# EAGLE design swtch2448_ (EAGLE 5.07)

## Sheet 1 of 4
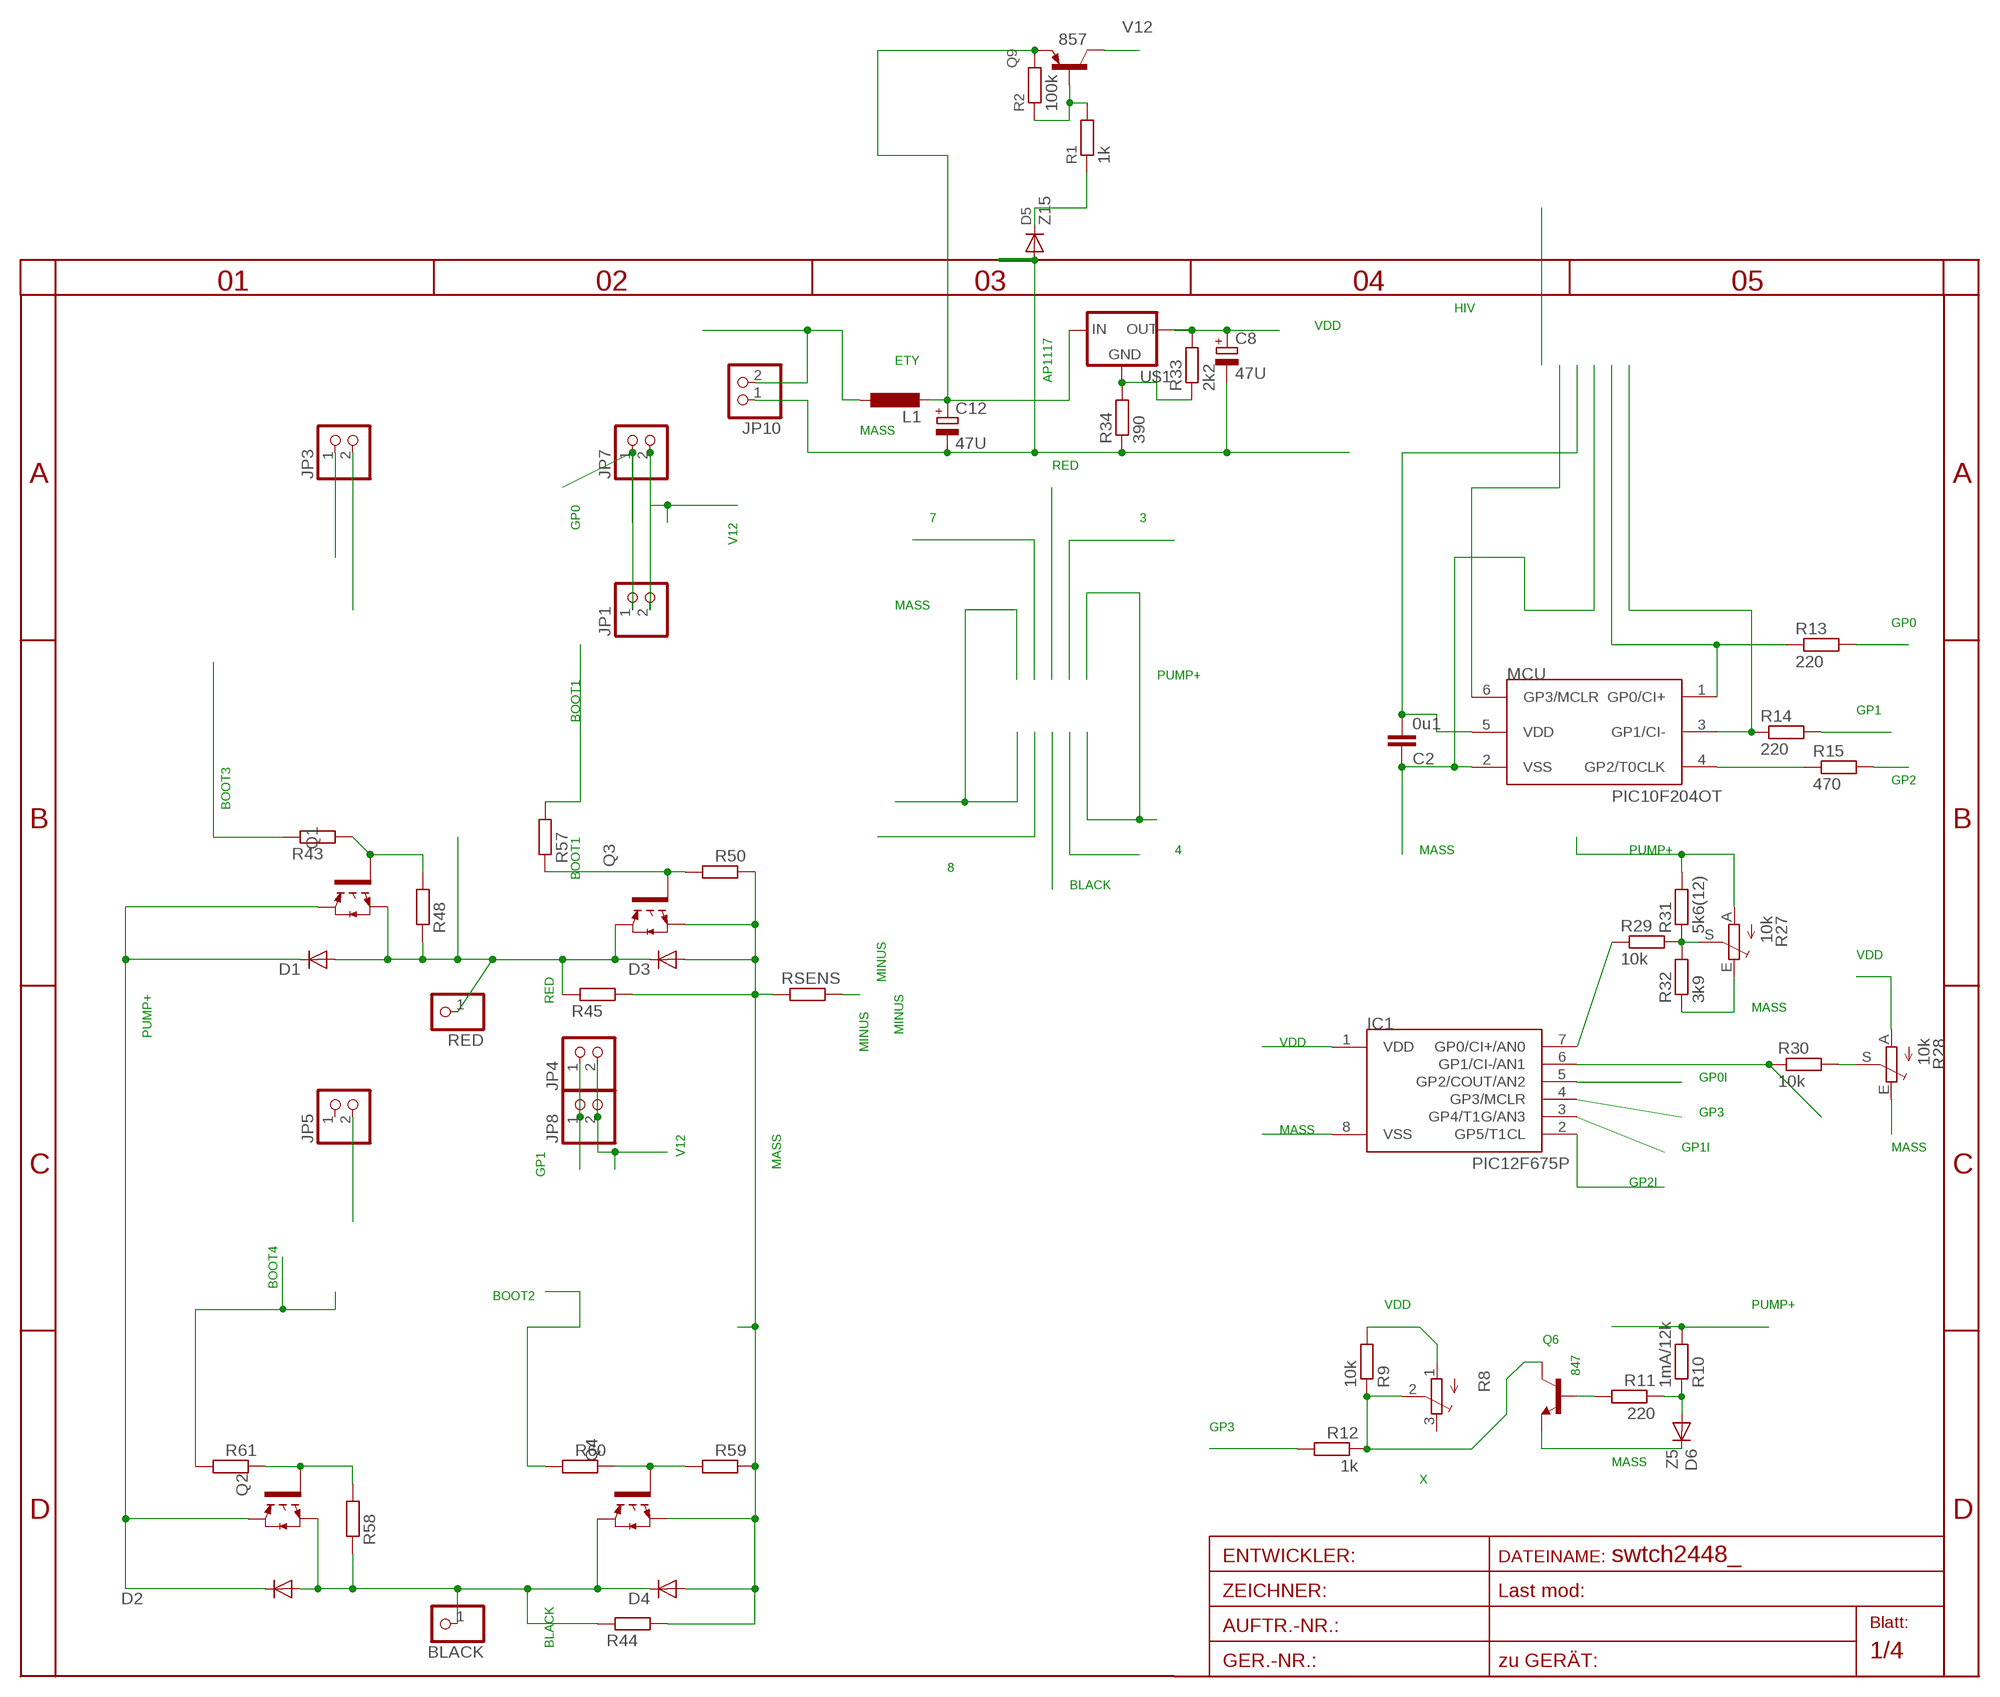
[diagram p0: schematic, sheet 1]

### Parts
BLACK  PINHD-1X14.5MM  [1X4MM5]
C2  0u1  C-EUC0805  [C0805]
C8  47U  CPOL-EUE  [PANASONIC_E]
C12  47U  CPOL-EUE  [PANASONIC_E]
D1  DIODE-SMC  [SMC]
D2  DIODE-SMC  [SMC]
D3  DIODE-SMC  [SMC]
D4  DIODE-SMC  [SMC]
D5  Z15  DIODE-MINIMELF  [MINIMELF]
D6  Z5  DIODE-MINIMELF  [MINIMELF]
IC1  PIC12F675P  [DIL8]
JP1  PINHD-1X2STR  [1X02]
JP3  PINHD-1X2STR  [1X02]
JP4  PINHD-1X2STR  [1X02]
JP5  PINHD-1X2STR  [1X02]
JP7  PINHD-1X2STR  [1X02]
JP8  PINHD-1X2STR  [1X02]
JP10  PINHD-1X2STR  [1X02]
L1  L-EU0204/5  [0204/5]
MCU  PIC10F204OT  [SOT23-6]
Q1  IRG4BC15UD-S  [D2PACK]
Q2  IRG4BC15UD-S  [D2PACK]
Q3  IRG4BC15UD-S  [D2PACK]
Q4  IRG4BC15UD-S  [D2PACK]
Q6  847  BC847ALT1SMD  [SOT23]
Q9  857  BC857ALT1SMD  [SOT23-BEC]
R1  1k  R-EU_R0805  [R0805]
R2  100k  R-EU_R0805  [R0805]
R8  TRIM_EU-3223W  [3223W]
R9  10k  R-EU_R1206  [R1206]
R10  1mA/12k  R-EU_R1206  [R1206]
R11  220  R-EU_R1206  [R1206]
R12  1k  R-EU_0204/7  [0204/7]
R13  220  R-EU_R1206  [R1206]
R14  220  R-EU_0207/10  [0207/10]
R15  470  R-EU_0207/20  [0207/20]
R27  10k  TRIM_EU-RAND160  [RANDL]
R28  10k  TRIM_EU-RAND160  [RANDL]
R29  10k  R-EU_0207/30  [0207/30]
R30  10k  R-EU_R0805  [R0805]
R31  5k6(12)  R-EU_0207/30  [0207/30]
R32  3k9  R-EU_R0805  [R0805]
R33  2k2  R-EU_R0805  [R0805]
R34  390  R-EU_R0805  [R0805]
R43  R-EU_0204/2V  [0204V]
R44  R-EU_0204/2V  [0204V]
R45  R-EU_0204/2V  [0204V]
R48  R-EU_R1206  [R1206]
R50  R-EU_R1206  [R1206]
R57  R-EU_0204/2V  [0204V]
R58  R-EU_R1206  [R1206]
R59  R-EU_R1206  [R1206]
R60  R-EU_0204/2V  [0204V]
R61  R-EU_0204/2V  [0204V]
RED  PINHD-1X14.5MM  [1X4MM5]
RSENS  R-EU_CERAM55  [CERAM55]
U$1  AP1117  [SOT223]

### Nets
BLACK: BLACK.1 D2.A D4.C Q2.3(E) Q4.2(C) R44.1 R58.1 ; also sheet 2
BOOT1: R57.2 ; also sheet 2
BOOT2: R60.2 ; also sheet 2
BOOT3: R43.1 ; also sheet 2
BOOT4: R61.2 ; also sheet 2
ETY: JP10.2 L1.1
GP0: JP1.1 JP7.1 R13.2 ; also sheet 2
GP0I: IC1.5(GP2/COUT/AN2) MCU.1(GP0/CI+) R13.1
GP1: JP3.1 JP4.1 JP8.1 R14.2 ; also sheet 2
GP1I: IC1.3(GP4/T1G/AN3) MCU.3(GP1/CI-) R14.1
GP2: R15.2 ; also sheet 2
GP2I: IC1.2(GP5/T1CL) MCU.4(GP2/T0CLK) R15.1
GP3: IC1.4(GP3/MCLR) MCU.6(GP3/MCLR) R12.2
MASS: C2.1 C8.- C12.- D3.A D4.A D5.A D6.C IC1.8(VSS) JP10.1 MCU.2(VSS) Q3.3(E) Q4.3(E) Q6.2(E) R27.E R28.E R32.1 R34.1 R44.2 R45.2 R50.1 R59.1 RSENS.1 ; also sheet 2
MINUS: RSENS.2 ; also sheet 2,3,4
N$1: C12.+ L1.2 Q9.E R2.2 U$1.3(IN)
N$2: Q9.B R1.2 R2.1
N$3: D5.C R1.1
N$4: D6.A R10.1 R11.1
N$5: Q6.1(B) R11.2
N$14: Q1.1(G) R43.2 R48.2
N$24: R28.S R30.2
N$30: R33.1 R34.2 U$1.1(GND)
N$31: IC1.6(GP1/CI-/AN1) R30.1
N$34: R27.S R29.2 R31.1 R32.2
N$35: IC1.7(GP0/CI+/AN0) R29.1
N$37: Q2.1(G) R58.2 R61.1
N$55: Q3.1(G) R50.2 R57.1
N$56: Q4.1(G) R59.2 R60.1
PUMP+: D1.C D2.C Q1.2(C) Q2.2(C) R10.2 R27.A R31.2 ; also sheet 2,3
RED: D1.A D3.C Q1.3(E) Q3.2(C) R45.1 R48.1 RED.1 ; also sheet 2
V12: JP1.2 JP3.2 JP4.2 JP5.2 JP7.2 JP8.2 Q9.C ; also sheet 2,4
VDD: C2.2 C8.+ IC1.1(VDD) MCU.5(VDD) R8.1(A) R9.2 R28.A R33.2 U$1.2(OUT) U$1.4(TAB)
X: Q6.3(C) R8.2(S) R9.1 R12.1
Unconnected: JP5.1 R8.3(E)

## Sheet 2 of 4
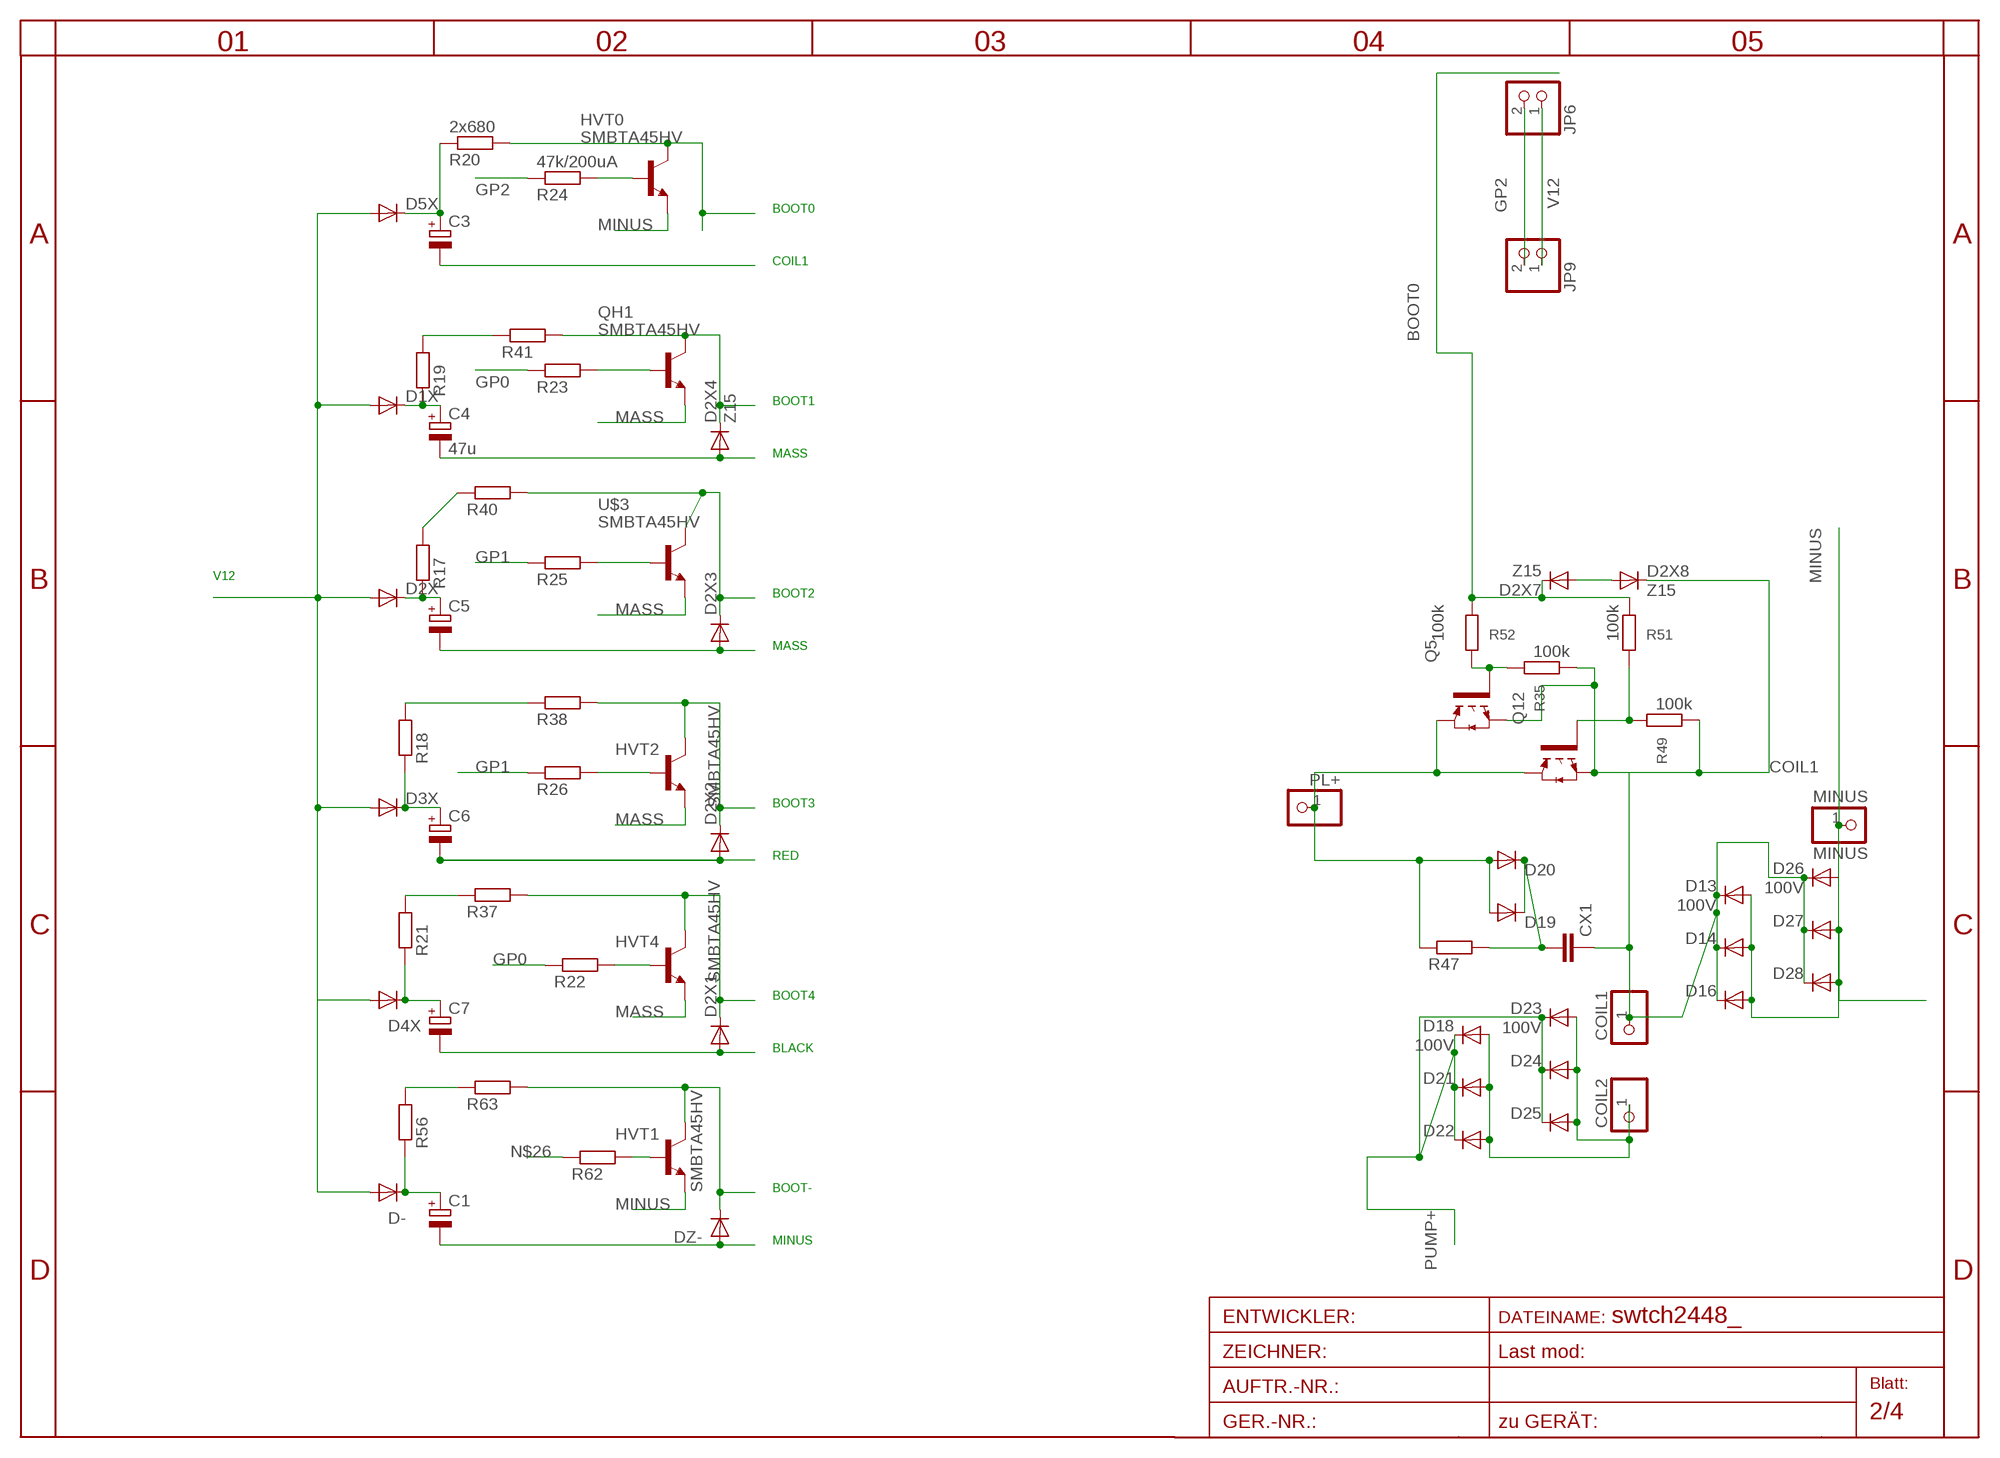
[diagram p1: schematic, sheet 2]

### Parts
C1  CPOL-EUE  [PANASONIC_E]
C3  CPOL-EUE  [PANASONIC_E]
C4  47u  CPOL-EUE  [PANASONIC_E]
C5  CPOL-EUE  [PANASONIC_E]
C6  CPOL-EUE  [PANASONIC_E]
C7  CPOL-EUE  [PANASONIC_E]
COIL1  PINHD-1X14.5MM  [1X4MM5]
COIL2  PINHD-1X14.5MM  [1X4MM5]
CX1  CXXC22B10  [XC22B10]
D1X  DIODE-SMA-DO214  [SMA-DO214AC]
D2X  DIODE-SMA-DO214  [SMA-DO214AC]
D2X1  DIODE-MINIMELF  [MINIMELF]
D2X2  DIODE-MINIMELF  [MINIMELF]
D2X3  DIODE-MINIMELF  [MINIMELF]
D2X4  Z15  DIODE-MINIMELF  [MINIMELF]
D2X7  Z15  DIODE-MINIMELF  [MINIMELF]
D2X8  Z15  DIODE-MINIMELF  [MINIMELF]
D3X  DIODE-SMA-DO214  [SMA-DO214AC]
D4X  DIODE-SMA-DO214  [SMA-DO214AC]
D5X  DIODE-SMA-DO214  [SMA-DO214AC]
D13  100V  DIODE-SMC  [SMC]
D14  DIODE-SMC  [SMC]
D16  DIODE-SMC  [SMC]
D18  100V  DIODE-SMC  [SMC]
D19  DIODE-SMC  [SMC]
D20  DIODE-SMC  [SMC]
D21  DIODE-SMC  [SMC]
D22  DIODE-SMC  [SMC]
D23  100V  DIODE-SMC  [SMC]
D24  DIODE-SMC  [SMC]
D25  DIODE-SMC  [SMC]
D26  100V  DIODE-SMC  [SMC]
D27  DIODE-SMC  [SMC]
D28  DIODE-SMC  [SMC]
D-  DIODE-SMA-DO214  [SMA-DO214AC]
DZ-  DIODE-MINIMELF  [MINIMELF]
HVT0  SMBTA45HV  [SOT23HV]
HVT1  SMBTA45HV  [SOT23HV]
HVT2  SMBTA45HV  [SOT23HV]
HVT4  SMBTA45HV  [SOT23HV]
JP6  PINHD-1X2STR  [1X02]
JP9  PINHD-1X2STR  [1X02]
MINUS  MINUS  PINHD-1X14.5MM  [1X4MM5]
PL+  PINHD-1X14.5MM  [1X4MM5]
Q5  IRG4BC15UD-S  [D2PACK]
Q12  IRG4BC15UD-S  [D2PACK]
QH1  SMBTA45HV  [SOT23HV]
R17  R-EU_R1206  [R1206]
R18  R-EU_R1206  [R1206]
R19  R-EU_R1206  [R1206]
R20  2x680  R-EU_R1206  [R1206]
R21  R-EU_R1206  [R1206]
R22  R-EU_R1206  [R1206]
R23  R-EU_R1206  [R1206]
R24  47k/200uA  R-EU_R1206  [R1206]
R25  R-EU_R1206  [R1206]
R26  R-EU_R1206  [R1206]
R35  100k  R-EU_R1206  [R1206]
R37  R-EU_R1206  [R1206]
R38  R-EU_R1206  [R1206]
R40  R-EU_R1206  [R1206]
R41  R-EU_R1206  [R1206]
R47  R-EU_0207/5V  [0207/5V]
R49  100k  R-EU_R1206  [R1206]
R51  100k  R-EU_0204/2V  [0204V]
R52  100k  R-EU_0204/2V  [0204V]
R56  R-EU_R1206  [R1206]
R62  R-EU_R1206  [R1206]
R63  R-EU_R1206  [R1206]
U$3  SMBTA45HV  [SOT23HV]

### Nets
BLACK: C7.- D2X1.A ; also sheet 1
BOOT0: D2X7.C HVT0.3(C) R20.2 R51.1 R52.1
BOOT1: D2X4.C QH1.3(C) R41.2 ; also sheet 1
BOOT2: D2X3.C R40.2 U$3.3(C) ; also sheet 1
BOOT3: D2X2.C HVT2.3(C) R38.2 ; also sheet 1
BOOT4: D2X1.C HVT4.3(C) R37.2 ; also sheet 1
BOOT-: DZ-.C HVT1.3(C) R63.2 ; also sheet 4
COIL1: C3.- COIL1.1 CX1.1 D2X8.C D13.C D14.C D16.C D26.C D27.C D28.C Q5.3(E) Q12.3(E) R35.1 R49.1
COIL2: COIL2.1 D18.A D21.A D22.A D23.A D24.A D25.A ; also sheet 4
GP0: R22.1 R23.1 ; also sheet 1
GP1: R25.1 R26.1 ; also sheet 1
GP2: JP6.2 JP9.2 R24.1 ; also sheet 1
HIV: D19.A D20.A D-.A PL+.1 Q5.2(C) Q12.2(C) R47.1 ; also sheet 1
MASS: C4.- C5.- D2X3.A D2X4.A HVT2.2(E) HVT4.2(E) QH1.2(E) U$3.2(E) ; also sheet 1
MINUS: C1.- D13.A D14.A D16.A D26.A D27.A D28.A DZ-.A HVT0.2(E) HVT1.2(E) MINUS.1 ; also sheet 1,3,4
N$13: C6.+ D3X.K(C) R18.1
N$15: C7.+ D4X.K(C) R21.1
N$16: C5.+ D2X.K(C) R17.1
N$17: C4.+ D1X.K(C) R19.1
N$18: C3.+ D5X.K(C) R20.1
N$19: HVT4.1(B) R22.2
N$20: HVT0.1(B) R24.2
N$21: QH1.1(B) R23.2
N$22: HVT2.1(B) R26.2
N$23: R25.2 U$3.1(B)
N$26: R62.1
N$38: R21.2 R37.1
N$39: R18.2 R38.1
N$40: R17.2 R40.1
N$41: R19.2 R41.1
N$44: D2X7.A D2X8.A
N$47: Q5.1(G) R35.2 R52.2
N$48: Q12.1(G) R49.2 R51.2
N$58: C1.+ D-.K(C) R56.1
N$59: HVT1.1(B) R62.2
N$61: R56.2 R63.1
PUMP+: D18.C D21.C D22.C D23.C D24.C D25.C ; also sheet 1,3
RED: C6.- D2X2.A ; also sheet 1
SNUB: CX1.2 D19.C D20.C R47.2
V12: D1X.A D2X.A D3X.A D4X.A D5X.A JP6.1 JP9.1 ; also sheet 1,4

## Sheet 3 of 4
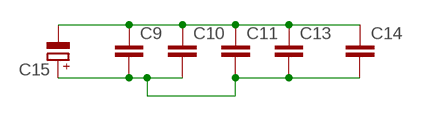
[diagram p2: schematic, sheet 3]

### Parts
C9  C-EUC1206  [C1206]
C10  C-EUC1206  [C1206]
C11  C-EUC1206  [C1206]
C13  C-EUC1206  [C1206]
C14  C-EUC1206  [C1206]
C15  CPOL-EUE2.5-7  [E2,5-7]

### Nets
MINUS: C9.1 C10.1 C11.1 C13.1 C14.1 C15.- ; also sheet 1,2,4
PUMP+: C9.2 C10.2 C11.2 C13.2 C14.2 C15.+ ; also sheet 1,2

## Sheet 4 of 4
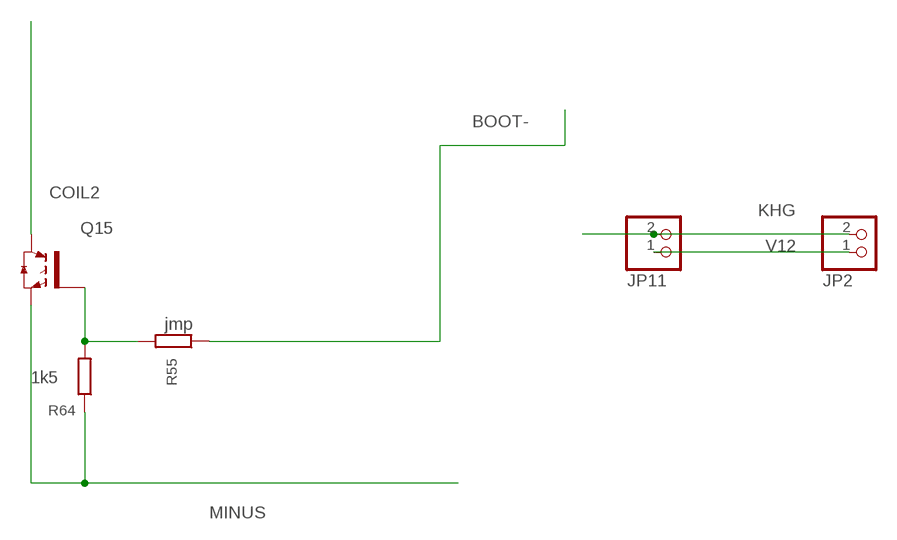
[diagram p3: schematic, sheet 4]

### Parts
JP2  PINHD-1X2STR  [1X02]
JP11  PINHD-1X2STR  [1X02]
Q15  IRG4BC15UD-S  [D2PACK]
R55  jmp  R-EU_0204/2V  [0204V]
R64  1k5  R-EU_R1206  [R1206]

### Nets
BOOT-: R55.1 ; also sheet 2
COIL2: Q15.2(C) ; also sheet 2
KHG: JP2.2 JP11.2
MINUS: Q15.3(E) R64.1 ; also sheet 1,2,3
N$53: Q15.1(G) R55.2 R64.2
V12: JP2.1 JP11.1 ; also sheet 1,2

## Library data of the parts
BLACK COIL1 COIL2 MINUS PL+ RED = pinhead:PINHD-1X1: PIN HEADER
C1 C3-C7 C15 = rcl:CPOL-EU: POLARIZED CAPACITOR, European symbol
C2 C9-C11 C13 C14 = rcl:C-EU: CAPACITOR, European symbol
C8 C12 = rcl-2:CPOL-EU: POLARIZED CAPACITOR, European symbol
CX1 = rcl:CX: X CAPACITOR
D1 D1X D2 D2X D2X1-D2X4 D2X7 D2X8 D3 D3X D4 D4X D5 D5X D6 D13 D14 D16 D18-D28 D- DZ- = diode:DIODE-: DIODE
HVT0 HVT1 HVT2 HVT4 QH1 U$3 = transistor-npn:SMBTA45
IC1 = microchip-5:PIC12F6*: uPC nW 1k Program Flash memory 2x Timer Comparator 10b A/D converter/ 4xIN
JP1-JP11 = pinhead:PINHD-1X2: PIN HEADER
L1 = rcl:L-EU: INDUCTOR, European symbol
MCU = microchip-3:PIC10F2*: uPC nW 0,25/0,5k Program Flash memory Comparator
Q1-Q5 Q12 Q15 = transistor-power:IRG4BC15UD-: INSULATED GATE BIPOLAR TRANSISTOR WITH ULTRAFAST SOFT RECOVERY DIODE
Q6 = transistor-npn:BC847*: NPN Transistor
Q9 = transistor-pnp:BC857*: PNP Transistror
R1 R2 R13-R15 R29-R35 R49 R51 R52 R55 R64 = rcl-2:R-EU_: RESISTOR, European symbol
R8 R27 R28 = pot:TRIM_EU-: POTENTIOMETER
R9-R12 R17-R26 R37 R38 R40 R41 R43-R45 R47 R48 R50 R56-R63 RSENS = rcl:R-EU_: RESISTOR, European symbol
U$1 = v-reg:AP1117

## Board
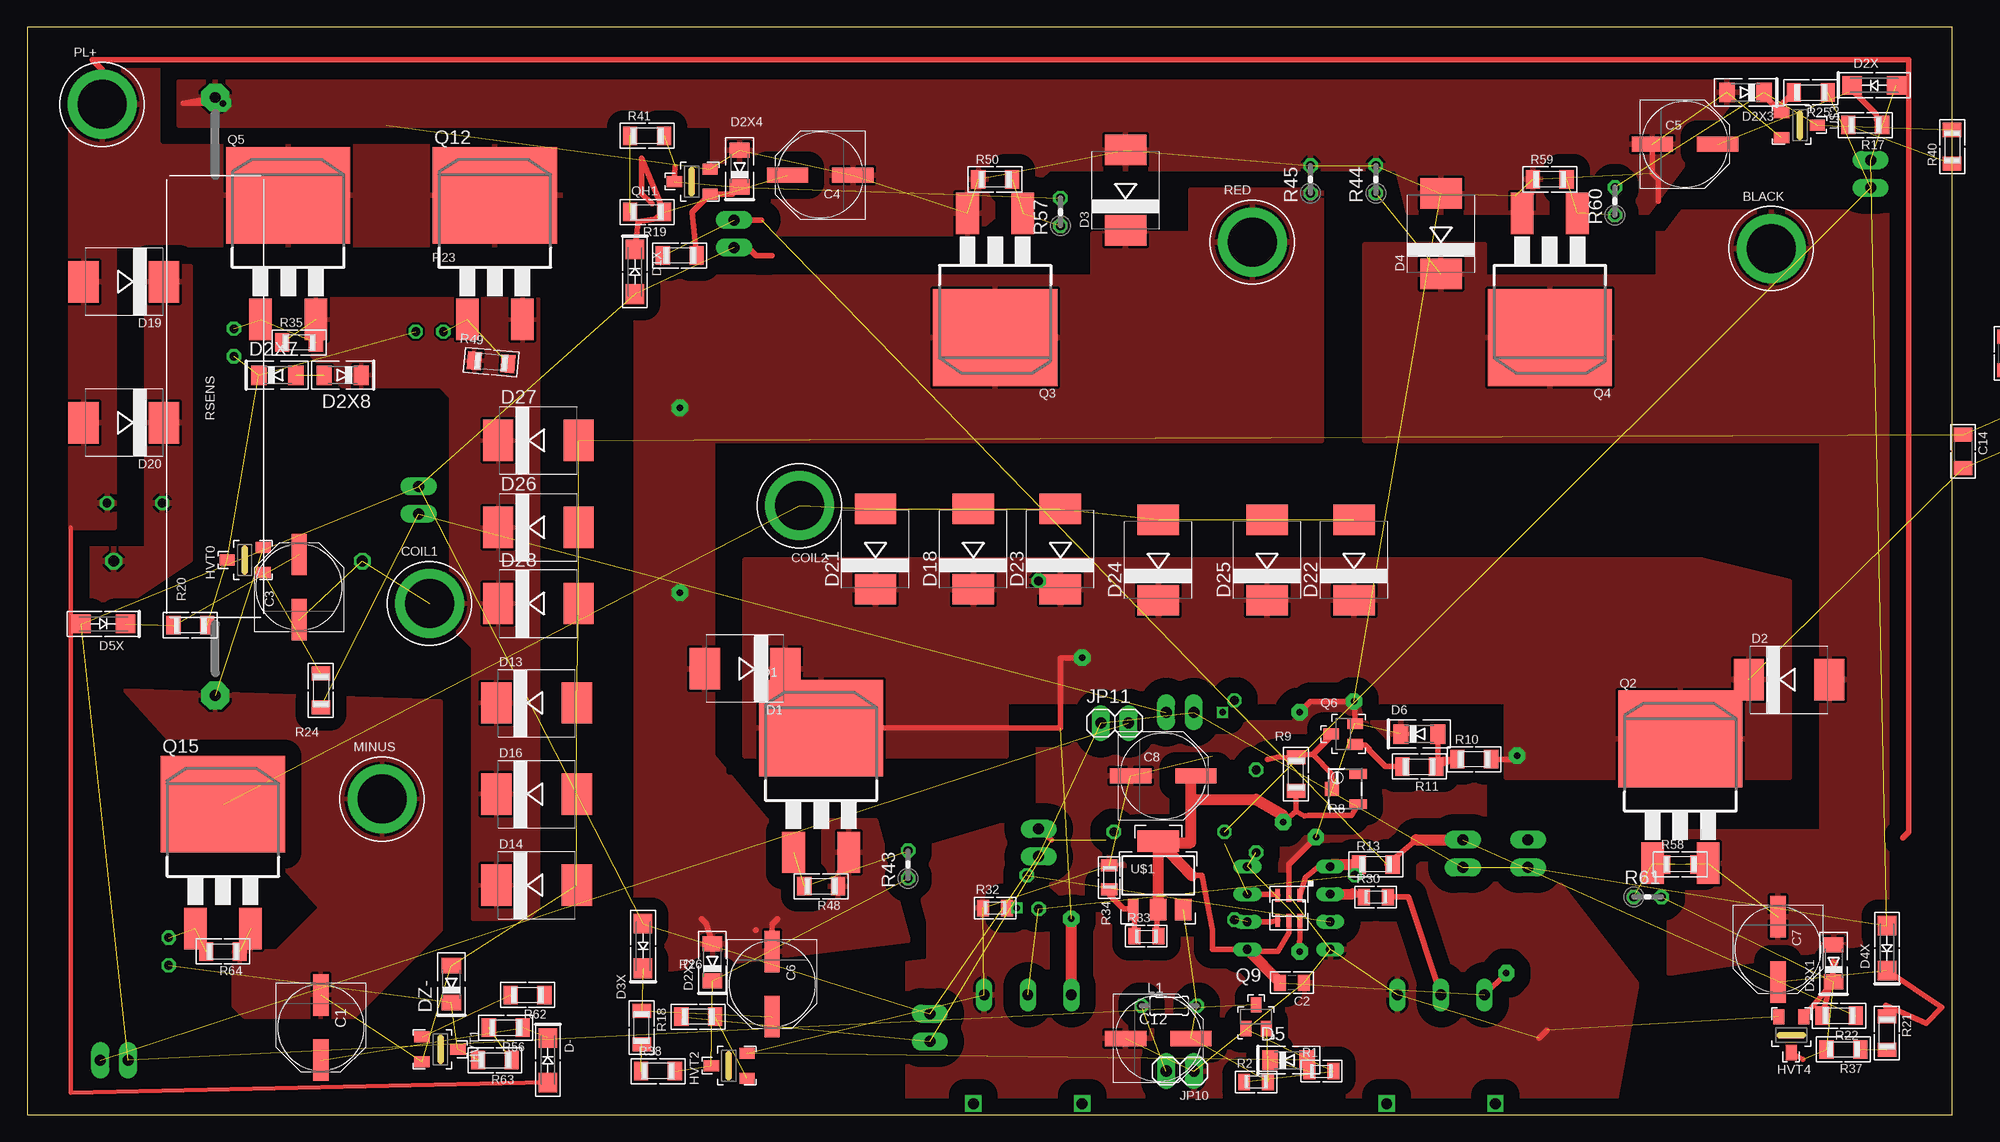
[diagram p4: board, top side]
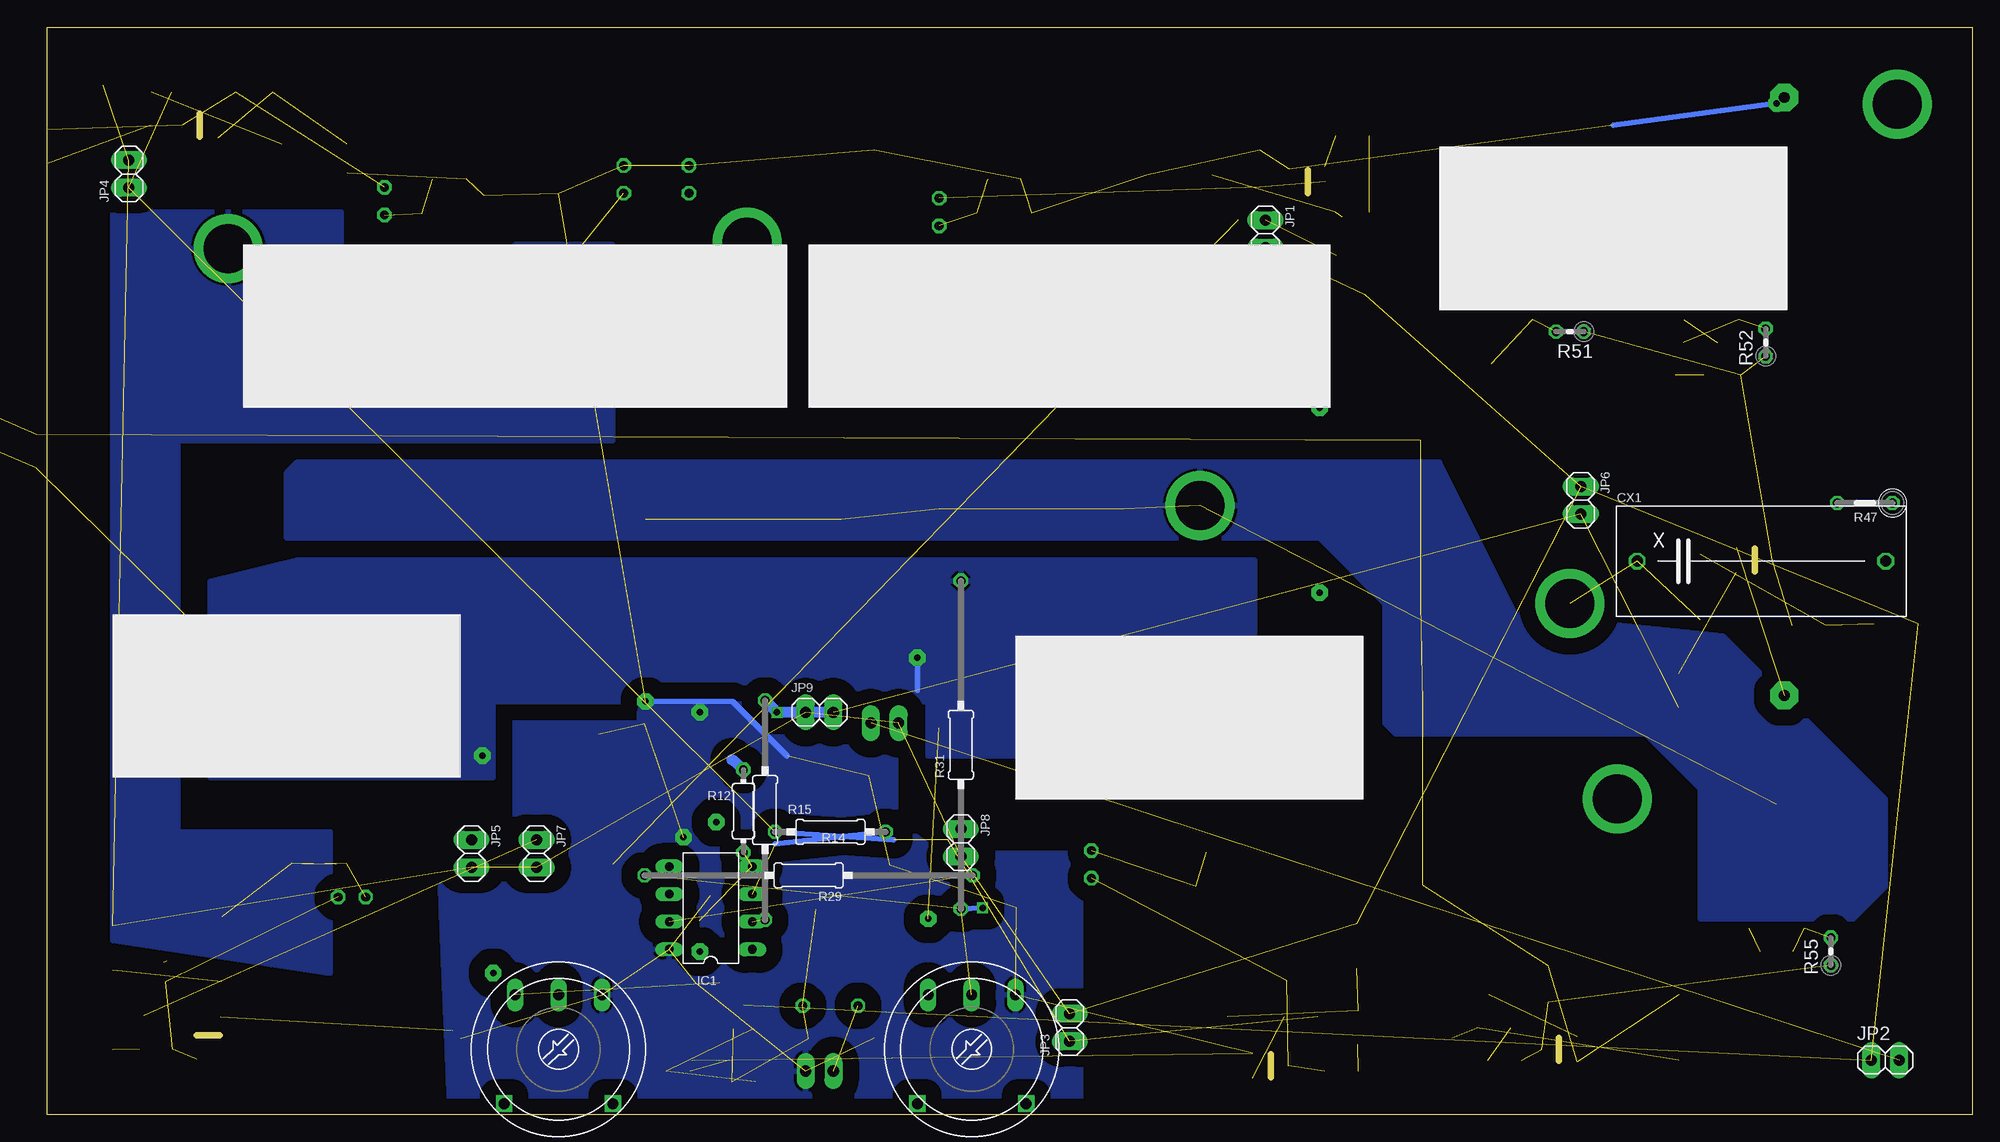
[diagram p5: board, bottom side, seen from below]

Size 177 x 100 mm. Coordinates in mm from the lower left corner, seen from the top.
Outline: 0,0 177,0 177,100 0,100 0,0
Copper layers (1*16): Top 0.035mm / dielectric 1.5mm / Bottom 0.035mm
Design rules "default *": minimum track width 10mil, minimum drill 20mil, track to track 8mil, track to pad 8mil, pad to pad 8mil, via to via 8mil, smd to smd 8mil, copper to edge 40mil, drill to drill 8mil, minimum pad ring 10mil, minimum via ring 8mil, stop-mask expansion 4mil, vias tented up to drill 0mil, thermal gap 10mil

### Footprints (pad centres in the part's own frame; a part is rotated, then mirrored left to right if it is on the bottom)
1X4MM5 = drill 4.5 pad 6.35 round: 1 0,0
PANASONIC_E = smd 3.8 x 1.4: + 3,0; - -3,0
C0805 = smd 1.1 x 1.5: 1 -1.1,0; 2 1.1,0
C1206 = smd 1.3 x 1.7: 1 -1.55,0; 2 1.55,0
E2,5-7 = drill 0.813 pad 1.6 round: + -1.27,0 | drill 0.813 pad 1.6 octagon: - 1.27,0
XC22B10 = drill 1.016 octagon: 1 -11.43,0.025; 2 11.43,0.025
SMC = smd 2.8 x 3.8: A 3.7,0; C -3.7,0
SMA-DO214AC = smd 1.8 x 1.7: A 2.05,-0.127; K -2.05,-0.127
MINIMELF = smd 1.4 x 1.8: A 1.7,0; C -1.7,0
SOT23HV = smd 1 x 1.4: 1 -1.15,-1.7; 2 1.15,-1.7; 3 0,1.6
DIL8 = drill 0.8 long: 1 -3.81,-3.81; 2 -1.27,-3.81; 3 1.27,-3.81; 4 3.81,-3.81; 5 3.81,3.81; 6 1.27,3.81; 7 -1.27,3.81; 8 -3.81,3.81
1X02 = drill 1.016 pad 1.676 long: 1 -1.27,0; 2 1.27,0
0204/5 = drill 0.813 octagon: 1 -2.54,0; 2 2.54,0
SOT23-6 = smd 0.45 x 1.2: 1 -1.016,-1.15; 2 0,-1.15; 3 1.016,-1.15; 4 1.016,1.15; 5 0,1.15; 6 -1.016,1.15
D2PACK = smd 2.083 x 3.81: 1 -2.54,-8.89; 3 2.54,-8.89 | smd 11.43 x 8.89: 2 0,2.54
SOT23 = smd 1 x 1.4: 1 -0.95,-1.1; 2 0.95,-1.1; 3 0,1.1
SOT23-BEC = smd 1 x 1.4: B -0.95,-1.1; C 0,1.1; E 0.95,-1.1
R0805 = smd 1.1 x 1.5: 1 -1.1,0; 2 1.1,0
3223W = smd 0.9 x 1.6: 1 -1.4,-1.215; 3 1.4,-1.215 | smd 1.3 x 1.3: 2 0,1.215
R1206 = smd 1.3 x 1.7: 1 -1.55,0; 2 1.55,0
0204/7 = drill 0.813 octagon: 1 -3.81,0; 2 3.81,0
0207/10 = drill 0.813 octagon: 1 -5.08,0; 2 5.08,0
0207/20 = drill 0.813 octagon: 1 -10.08,0; 2 10.08,0
RANDL = drill 1 long: A -4,5; E 4,5; S 0,5 | drill 1 square: P$1 -5,-5; P$2 5,-5
0207/30 = drill 0.813 octagon: 1 -15.08,0; 2 15.08,0
0204V = drill 0.813 octagon: 1 -1.27,0; 2 1.27,0
0207/5V = drill 0.813 octagon: 1 -2.54,0; 2 2.54,0
0204V' = drill 0.8 pad 1.27 octagon: 1 -1.27,0; 2 1.27,0
CERAM55 = drill 1 pad 2.54 octagon: 1 -27.5,0; 2 27.5,0
SOT223 = smd 1 x 2: 1 -2.3,-3.15 | smd 1.5 x 2: 2 0,-3.15; 3 2.3,-3.15 | smd 3.8 x 2: 4 0,3.15

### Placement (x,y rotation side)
BLACK  160.35,79.64 0 top
C1  27,8 270 top
C2  116.3,12.12 180 top
C3  25,48.5 90 top
C4  72.92,86.38 180 top
C5  152.43,89.25 0 top
C6  68.5,12 270 top
C7  160.98,15.19 270 top
C8  104.46,31.15 0 top
C9  not placed on the board
C10  not placed on the board
C11  not placed on the board
C12  104,7 0 top
C13  not placed on the board
C14  178,61 270 top
C15  not placed on the board
COIL1  37,47 0 top
COIL2  71,56 180 top
CX1  19.39,50.87 0 bottom
D1  66,41 180 top
D1X  56,77.5 270 top
D2  162,40 0 top
D2X  169.83,94.78 0 top
D2X1  166.1,13.9 90 top
D2X2  63,14 90 top
D2X3  158,94 180 top
D2X4  65.5,87 90 top
D2X7  23,68 0 top
D2X8  29,68 180 top
D3  101,85 90 top
D3X  56.5,15.5 90 top
D4  130,81 90 top
D4X  170.88,15.31 90 top
D5  116,5 0 top
D5X  7,45 180 top
D6  128,35 0 top
D13  46.84,37.85 0 top
D14  46.84,21.09 0 top
D16  46.84,29.47 0 top
D18  87,52 90 top
D19  8.88,76.59 180 top
D20  8.88,63.62 180 top
D21  78,52 90 top
D22  122,51 90 top
D23  95,52 90 top
D24  104,51 90 top
D25  114,51 90 top
D26  47,54 0 top
D27  47,62 0 top
D28  47,47 0 top
D-  48,5 270 top
DZ-  39,12 90 top
HVT0  20,51 90 top
HVT1  38,6 270 top
HVT2  64.5,4.5 90 top
HVT4  162.2,7.3 180 top
IC1  116,19 90 bottom
JP1  65,81 270 bottom
JP2  8,5 0 bottom
JP3  83,8 90 bottom
JP4  169.5,86.5 90 bottom
JP5  138,24 270 bottom
JP6  36,56.5 270 bottom
JP7  132,24 270 bottom
JP8  93,25 270 bottom
JP9  106,37 0 bottom
JP10  106,4 180 top
JP11  100,36 0 top
L1  105,10 0 top
MCU  116,19 180 top
MINUS  32.62,29.02 0 top
PL+  6.89,92.9 0 top
Q1  73,33 0 top
Q2  152,32 0 top
Q3  89,74 180 top
Q4  140,74 180 top
Q5  24,82 0 top
Q6  121,35 90 top
Q9  113,9 0 top
Q12  43,82 0 top
Q15  18,26 0 top
QH1  61.1,85.8 90 top
R1  119,4 0 top
R2  113,3 0 top
R8  121.18,29.94 90 top
R9  116.67,31.3 270 top
R10  133.05,32.67 0 top
R11  128,32 180 top
R12  113,27.9 270 bottom
R13  124,23 0 top
R14  105,26 180 bottom
R15  111,28 90 bottom
R17  169,91 180 top
R18  56.5,8 270 top
R19  57,83 180 top
R20  15,45 0 top
R21  171,7.5 270 top
R22  166.6,9.1 180 top
R23  60,79 0 top
R24  27,39 90 top
R25  164,94 180 top
R26  61.7,9 0 top
R27  92,6 0 bottom
R28  130,6 0 bottom
R29  107,22 180 bottom
R30  124,20 0 top
R31  93,34 90 bottom
R32  89,19 0 top
R33  102.9,16.4 0 top
R34  99.5,21.8 270 top
R35  25,71 0 top
R37  167,6 180 top
R38  58,4 0 top
R40  177,89 90 top
R41  57,90 0 top
R43  81,23 90 top
R44  124,86 90 top
R45  118,86 90 top
R47  9.88,56.24 180 bottom
R48  73,21 180 top
R49  42.66,69.19 355 top
R50  89,86 0 top
R51  100k  [0204V']  37,72 180 bottom
R52  100k  [0204V']  19,71 90 bottom
R55  jmp  [0204V']  13,15 90 bottom
R56  44,8 180 top
R57  95,83 90 top
R58  152,23 0 top
R59  140,86 0 top
R60  146,84 90 top
R61  149,20 0 top
R62  46,11 180 top
R63  43,5 180 top
R64  18,15 180 top
RED  112.65,80.23 0 top
RSENS  17.29,66.04 270 top
U$1  104,22 0 top
U$3  163,91 270 top

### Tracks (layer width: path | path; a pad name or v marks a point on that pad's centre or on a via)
BLACK  (3 unrouted)
  pour Top (isolate 1.5, rank 2): 123,80 134,80 134,77 150,77 150,83 171,83 171,16 151,13 151,26 165,26 165,62 123,62
  pour Bottom (isolate 1.5, rank 2): 125,80 134,80 134,77 150,77 150,83 171,83 171,16 151,13 151,26 165,26 165,62 125,62
BOOT0  (4 unrouted)
BOOT1  (3 unrouted)
  Top 0.5: QH1.3 59.55,87.15
BOOT2  (3 unrouted)
BOOT3  (3 unrouted)
BOOT4  (3 unrouted)
  Top 0.5: HVT4.3 163.25,5.1
BOOT-  (3 unrouted)
COIL1  (3 unrouted)
  pour Top: 26,75 47,75 47,19 46,18 41,18 41,43 39,45 39,66 38,67 29,67 26,70
COIL2  (7 unrouted)
  pour Bottom (isolate 1.5): 155,53 60,53 54,47 54,36 53,35 30,35 25,30 25,18 11,18 8,21 8,29 23,44 42,46 49,60 154,60 155,59
ETY  (1 unrouted)
GP0  (3 unrouted)
  Top 0.5: R13.2 125,23 127.73,25.27 | JP1.1 67.53,82.27
  Top 1: 127.73,25.27 JP7.1
GP0I
  Top 0.5: MCU.1 117.52,21.82 119,23 119.62,23 IC1.5 120,23
  Top 1: 120,23 R13.1
GP1  (5 unrouted)
  Top 0.5: JP8.1 94.19,25.27
  Bottom 0.5: 99.19,25.27 R14.2
GP1I  (1 unrouted)
  Top 0.5: IC1.3 114.6,20.27 MCU.3
  Bottom 0.5: R14.1 110.1,24.9
GP2  (via drill 0.6)  (2 unrouted)
  Bottom 1: JP9.2 v109.92,37 R15.2
GP2I  (1 unrouted)
  Top 0.5: IC1.2 114.36,17.73 MCU.4
  Bottom 0.5: R15.1 111.08,18
GP3  (via drill 0.6 pad 1.5)  (2 unrouted)
  Top 0.5: MCU.6 117.02,16.98 v117,15
  Bottom 0.5: R12.2 113.2,24.2
HIV
  Top 0.406: 4,54 4,45 4,2 D-.A
  Top 0.5: 172.44,25.44 173,26 173,95 | 173,95 173,97 6,97 6.89,96.11 PL+.1 | 173,95 172.65,94.65
  pour Top (isolate 1.5, rank 2): 4,96 49,96 49,80 8,80 8,54 4,54
KHG  (1 unrouted)
MASS  (via drill 0.6 pad 1.5)  (30 unrouted)
  Top 0.5: Q4.3 136.83,84.52 | MCU.2 116,23 v118.5,25.5 | Q6.2 122.1,37.9 v122,38 118,38 v117,37 | 139,7 139.75,7.75 | v18,93 14.33,93 RSENS.1 | C5.- 149.43,86.57 150,86 150,84
  Bottom 0.5: v122,38 114,38 109,33 | v18,93 33,91
  pour Top (isolate 1.5): 14,95 158,95 149,83 127,83 126,87 94,87 87,81 69,81 65,82 65,87 63,87 63,91 14,91
  pour Top (isolate 1.5, rank 3): 93,38 134,38 134,25 138,25 148,12 146,1 81,1 81,24 91,27 93,27
  pour Bottom (isolate 1.5, rank 3): 99,38 134,38 134,25 141,25 140,1 82,1 82,24 95,24 99,27
MINUS  (16 unrouted)
  pour Top (isolate 1.5): 9,39 38,38 38,17 30,9 20,9 19,10 19,15 23,15 27,19
N$1  (4 unrouted)
N$2  (2 unrouted)
N$3  (1 unrouted)
N$4
  Top 0.5: R10.1 130.22,32.67 131.28,32.73 | R11.1 131.28,32.73 | D6.A 129.7,32.3 131.28,32.73
N$5
  Top 0.5: R11.2 124.9,32 123.4,33.5 123.4,33.6 123,34 122.15,34 Q6.1
N$13  (2 unrouted)
N$14  (2 unrouted)
N$15  (1 unrouted)
  Top 0.5: D4X.K 176.06,9.86 174.6,8.4 170.9,10.05 R21.1
N$16  (1 unrouted)
  Top 0.5: D2X.K 167.43,94 168,94 170,92 170,91.55 R17.1
N$17  (2 unrouted)
  Top 0.5: D1X.K 56.17,82.13 57.9,82.4 57.9,82.55 | 57.45,83.75 56.5,84.7 56.5,87.95 R19.1
N$18  (2 unrouted)
N$19  (1 unrouted)
  Top 0.5: R22.2 166.3,14 | HVT4.1 165.35,11.35 166,12 166,14.1
N$20  (1 unrouted)
N$21
  Top 0.5: R23.2 61.15,83 QH1.1 64.85,84.65
N$22  (1 unrouted)
  Top 0.5: R26.2 63,9.55
N$23
  Top 0.5: 159.7,93.75 U$3.1 161.3,92.85 R25.2
N$24
  Top 0.5: R28.S 127,20 R30.2
N$30
  Top 0.5: R33.1 101.8,18.75 U$1.1 101.65,18.9 100.8,18.9 99.5,20.2 R34.2
N$31
  Top 0.5: 121.88,20.3 R30.1
  Top 1: IC1.6 121.88,20.3
N$34  (via drill 0.6)  (2 unrouted)
  Top 0.5: R32.2 v91,19
  Bottom 0.5: v91,19 R31.1
N$35  (1 unrouted)
N$37  (2 unrouted)
N$38  (1 unrouted)
N$39  (1 unrouted)
N$40  (1 unrouted)
N$41  (1 unrouted)
N$44  (1 unrouted)
N$47  (2 unrouted)
N$48  (2 unrouted)
N$53  (2 unrouted)
N$55  (2 unrouted)
N$56  (2 unrouted)
N$58  (2 unrouted)
N$59  (1 unrouted)
N$61  (1 unrouted)
PUMP+  (via drill 0.6 pad 1.5)  (7 unrouted)
  Top 0.5: R10.2 136.67,32.67 v137,33 | Q1.2 95,35.54 95,42 v97,42
  Top 1: R27.A v96,18
  Bottom 0.5: v97,42 97,39
  pour Top (isolate 1.5): 162,49 162,31 136,31 136,38 90,38 90,33 66,33 66,51 154,51
  pour Bottom (isolate 1.5): 162,49 162,31 136,31 136,38 96,38 96,33 66,33 66,51 154,51
RED  (via drill 0.6 pad 1.5)
  Top 0.5: 66.95,16.95 67,17 | D2X2.A 62.4,17.6 62,18 | C6.- 68.5,17.5 69,18
  other vias: 60,65 60,48
  pour Top (isolate 1.5, rank 2): 119,62 119,85 107,85 107,81 98,81 98,77 56,77 56,13 81,16 78,27 68,27 63,33 63,62
SNUB
  pour Top (isolate 1.5, rank 2): 11,78 15,78 15,51 9,47 5,47 5,52 11,52
V12  (15 unrouted)
  Top 0.5: JP1.2 66.27,79.73 67,79 68.5,79
VDD  (via drill 0.6 pad 1.5)  (1 unrouted)
  Top 0.5: MCU.5 116,16.7 115,15 112.38,15 IC1.1 109,15.19 109,17 108,22 107.06,21.99 | R28.A v136,13 | 116.67,27.87 R9.2 | 116.67,27.87 v115.5,26.9 115.5,27.5 | 116.67,27.87 117.43,27.47 117.8,27.5 121.75,27.5 R8.1 | 115.2,12.18 C2.2 | R33.2 103.8,16.8 U$1.2 | U$1.4 104,25
  Top 1: IC1.1 115.2,12.18 | 115.5,27.5 113,29 107,29 | U$1.2 U$1.4 107.06,21.99 | 104,25 107,25 107,29 | 107,29 107,30.61 C8.+
X  (1 unrouted)
  Top 0.5: R8.2 119.97,31.34 118.2,33.1 | 118.2,33.1 116.92,33.1 R9.1 116.52,32.7 115.1,32.9 114.05,32.65 | Q6.3 119.9,34.8 118.2,33.1
  Bottom 1: R12.1 114.05,32.65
